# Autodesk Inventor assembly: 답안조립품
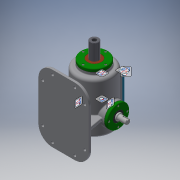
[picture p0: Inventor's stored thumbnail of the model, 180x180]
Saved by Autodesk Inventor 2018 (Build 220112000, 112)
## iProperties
Created: 2019-10
Part Number: 답안조립품
Document SubType Name: Assembly
Designer: expoc
Author: expoc
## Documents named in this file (19)
- C:\Users\expoc\Desktop\391004V1034\답안조립품.iam
- C:\Users\expoc\Desktop\391004V1034\본체.ipt
- C:\Users\expoc\Desktop\391004V1034\편심축.ipt
- C:\Users\expoc\Desktop\391004V1034\베어링 6205.ipt
- 베어링 6205.ipt
- C:\Users\expoc\Desktop\391004V1034\축 커버.ipt
- C:\Users\expoc\Desktop\391004V1034\오일 실 25 38 8.ipt
- C:\Users\expoc\Desktop\391004V1034\개스킷 B.ipt
- C:\Users\expoc\Desktop\391004V1034\개스킷 B_MIR.ipt
- C:\Users\expoc\Desktop\391004V1034\축 커버_MIR.ipt
- C:\Users\expoc\Desktop\391004V1034\슬라이드.ipt
- C:\Users\expoc\Desktop\391004V1034\부시.ipt
- C:\Users\expoc\Desktop\391004V1034\슬라이드 커버.ipt
- C:\Users\expoc\Desktop\391004V1034\개스킷 A.ipt
- C:\Users\expoc\Desktop\391004V1034\가변스프링.ipt
- C:\Users\expoc\Desktop\391004V1034\고정플레이트.ipt
- C:\Users\expoc\Desktop\391004V1034\상부커버.ipt
- C:\Users\expoc\Desktop\391004V1034\볼트 M4x0.7.ipt
- C:\Users\expoc\Desktop\391004V1034\육각머리볼트 M4.ipt
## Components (17 placed, 6 different names)
1. 개스킷 B:1
2. 개스킷 B_MIR:1
3. 개스킷 A:1
4. 가변스프링:1
5. 고정플레이트:1
6. M4x0.7:5
7. M4x0.7:6
8. M4x0.7:7
9. M4x0.7:8
10. M4x0.7:1
11. M4x0.7:2
12. M4x0.7:3
13. M4x0.7:4
14. M4x0.7:9
15. M4x0.7:10
16. M4x0.7:11
17. M4x0.7:12
